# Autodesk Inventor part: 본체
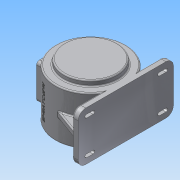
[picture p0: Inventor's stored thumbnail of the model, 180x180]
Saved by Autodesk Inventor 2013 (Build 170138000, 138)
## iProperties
Created: 2015-06
Part Number: 본체
Material: 알루미늄 6061
Document SubType Name: Modeling
Designer: Administrator
Density: 2.71 g/cm^3
Mass: 3338.13 g
Surface Area: 2328.16 cm^2
Volume: 1231.78 cm^3
Author: Administrator
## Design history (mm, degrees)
sketch "스케치2"
  geometry: C1 r 85 at (0, 0); 1 further point
  constraints: 1 centre point, 1 coincident
  dimensions: "d6" = 170 diameter of C1
extrude "돌출2" new body sketch "스케치2" distance "d7" = 118; taper "d8" = 0 deg
sketch "스케치3"
  geometry: C1 r 85 at (0, 0) reference; C2 r 65 at (0, 0)
  constraints: 1 centre point, 1 coincident
  dimensions: "d9" = 130 diameter of C2
extrude "돌출3" join sketch "스케치3" distance "d10" = 13; taper "d11" = 0 deg
sketch "스케치4"
  geometry: C1 r 85 at (0, 0) reference; C2 r 65 at (0, 0)
  constraints: 1 centre point, 1 coincident
  dimensions: "d12" = 130 diameter of C2
extrude "돌출4" join sketch "스케치4" distance "d13" = 3; taper "d14" = 0 deg
sketch "스케치8"
  geometry: L1 (-85, 0)-(-85, 118) reference; L2 (-85, 118)-(-65, 118) reference; L3 (-65, 118)-(-65, 131) reference; L4 (-65, 131)-(65, 131) reference; L5 (65, 131)-(65, 118) reference; L6 (65, 118)-(85, 118) reference; L7 (85, 118)-(85, 0) reference; L8 (85, 0)-(65, 0) reference; L9 (65, 0)-(65, -3) reference; L10 (65, -3)-(-65, -3) reference; L11 (-65, -3)-(-65, 0) reference; L12 (-65, 0)-(-85, 0) reference; L13 (15, 123.5)-(15, 120.5); L14 (15, 120.5)-(23.5, 120.5); L15 (23.5, 120.5)-(23.5, 106.5); L16 (23.5, 106.5)-(29.368, 106.5); L17 (29.368, 106.5)-(31, 110); L18 (31, 110)-(77, 110); L19 (77, 110)-(77, 8); L20 (77, 8)-(47.5, 8); L21 (47.5, 8)-(47.5, -3); L22 (15, 123.5)-(0, 123.5); L23 (0, 123.5)-(0, -3); L24 (47.5, -3)-(0, -3); 1 further point
  constraints: 24 end point, 2 perpendicular, 1 collinear, 1 midpoint, 1 point on line
  dimensions: "d64" = 3 distance between parallel lines of L14 L22; "d65" = 14 distance between parallel lines of L16 L14; "d66" = 3.5 distance between parallel lines of L16 L18; "d67" = 115 deg angle of L16 L17; "d68" = 102 distance between parallel lines of L18 L20; "d70" = 7.5 distance between parallel lines of L22 L4; "d71" = 154 diameter of L19 L23; "d72" = 47 diameter of L15 L23; "d73" = 30 diameter of L13 L23; "d74" = 62 diameter of L17.end L23; "d75" = 95 diameter of L21 L23
  node "절단 모서리 투영2"
revolve "회전1" stored, may be unused: angle "d76" = 90 deg
node "작업 평면2"
sketch "스케치9"
  geometry: L1 (-97, 118)-(97, 118); L2 (115, 100)-(115, 18); L3 (97, 0)-(-97, 0); L4 (-115, 18)-(-115, 100); L5 (0, 0)-(0, 118) reference; A1 r 18 centre (-97, 100) between (-97, 118) and (-115, 100); A2 r 18 centre (-97, 18) between (-115, 18) and (-97, 0); A3 r 18 centre (97, 18) between (97, 0) and (115, 18); A4 r 18 centre (97, 100) between (115, 100) and (97, 118); 6 further points
  constraints: 8 end point, 8 point on circle, 8 tangent, 6 point on line, 4 centre point, 3 equal radius, 3 midpoint, 2 parallel, 1 coincident, 1 horizontal, 1 horizontal alignment, 1 perpendicular
  dimensions: "d78" = 230 distance of point (-115, 118) point (115, 118); "d80" = 118 distance of point (-115, 0) point (-115, 118); "d81" = 18 radius of A1
extrude "돌출6" join sketch "스케치9" distance "d82" = 14; taper "d83" = 0 deg
sketch "스케치10"
  geometry: L1 (118, 46.733)-(118, 97) reference; L2 (0, 97)-(0, 46.733) reference; L3 (91, 97)-(91, 81); L4 (109, 81)-(109, 97); L5 (18, 115)-(100, 115) reference; L6 (118, 97)-(118, 46.733) reference; L7 (0, 46.733)-(118, 46.733) reference; L8 (0, -46.733)-(0, 46.733) reference; L9 (118, -46.733)-(0, -46.733) reference; L10 (118, -46.733)-(118, -97) reference; L11 (100, -115)-(18, -115) reference; L12 (0, -97)-(0, -46.733) reference; L13 (0, 46.733)-(0, 97) reference; L14 (118, 46.733)-(118, -46.733) reference; L15 (8, 29.799)-(8, -29.799) reference; L16 (8, -29.799)-(110, -29.799) reference; L17 (110, -29.799)-(110, 29.799) reference; L18 (110, 29.799)-(8, 29.799) reference; L19 (96, 97)-(96, 81); L20 (104, 81)-(104, 97); A1 r 18 centre (100, 97) between (118, 97) and (100, 115) reference; A2 r 9 centre (100, 81) between (91, 81) and (109, 81); A3 r 9 centre (100, 97) between (109, 97) and (91, 97); A4 r 18 centre (18, 97) between (18, 115) and (0, 97) reference; A5 r 18 centre (100, 97) between (118, 97) and (100, 115) reference; A6 r 18 centre (100, -97) between (100, -115) and (118, -97) reference; A7 r 18 centre (18, -97) between (0, -97) and (18, -115) reference; A8 r 4 centre (100, 81) between (96, 81) and (104, 81); A9 r 4 centre (100, 97) between (104, 97) and (96, 97); 1 further point
  constraints: 8 end point, 8 point on circle, 4 centre point, 3 tangent, 2 parallel, 1 coincident, 1 equal radius, 3 other
  dimensions: "d84" = 18 distance between parallel lines of L4 L3; "d86" = 16 distance of A2.centre A1.centre; "d87" = 8 distance between parallel lines of L20 L19
  node "절단 모서리 투영4"
extrude "돌출7" join sketch "스케치10" distance "d88" = 3; taper "d89" = 0 deg
extrude "돌출8" cut sketch "스케치10" distance "d90" = 3; taper "d92" = 0 deg; dims "d91" = 14, "d93" = 0
node "작업 평면3"
sketch "스케치11"
  geometry: L1 (71, -29.799)-(71, 29.799) reference; L2 (71, 46.733)-(71, 115) reference; L3 (71, 115)-(85, 115) reference; L4 (85, 115)-(85, -115) reference; L5 (85, -115)-(71, -115) reference; L6 (71, -115)-(71, -46.733) reference; L7 (71, -109)-(4.703, -84.87); L8 (71, 109)-(4.703, 84.87); A1 r 77 centre (0, 0) between (71, 29.799) and (71, -29.799) reference; A2 r 85 centre (0, 0) between (71, 46.733) and (71, -46.733) reference; 1 further point
  constraints: 4 end point, 2 point on circle, 2 point on line
  dimensions: "d101" = 6 distance of L7.start L5.end; "d102" = 110 deg angle of L7 L6; "d103" = 6 distance of L2.end L8.start; "d104" = 110 deg angle of L2 L8
  node "절단 모서리 투영5"
feature "리브1" dims "d105" = 1, "d106" = 15, "d107" = 0, "d108" = 0, "d109" = 1, "d110" = 1
feature "리브2" dims "d111" = 1, "d112" = 15, "d113" = 0, "d114" = 0, "d115" = 1, "d116" = 1
node "작업 평면4"
sketch "스케치12"
  geometry: L1 (-35.5, 101.5)-(35.5, 101.5); L2 (42.5, 94.5)-(42.5, 23.5); L3 (35.5, 16.5)-(-35.5, 16.5); L4 (-42.5, 23.5)-(-42.5, 94.5); L5 (115, 18)-(115, 100) reference; A1 r 7 centre (-35.5, 94.5) between (-35.5, 101.5) and (-42.5, 94.5); A2 r 7 centre (-35.5, 23.5) between (-42.5, 23.5) and (-35.5, 16.5); A3 r 7 centre (35.5, 23.5) between (35.5, 16.5) and (42.5, 23.5); A4 r 7 centre (35.5, 94.5) between (42.5, 94.5) and (35.5, 101.5); 8 further points
  constraints: 8 end point, 8 point on circle, 8 point on line, 8 tangent, 4 centre point, 3 equal radius, 3 midpoint, 2 parallel, 1 horizontal, 1 horizontal alignment, 1 perpendicular, 1 vertical alignment
  dimensions: "d118" = 85 distance between parallel lines of L2 L4; "d120" = 85 distance between parallel lines of L1 L3; "d127" = 7 radius of A1
extrude "돌출9" join sketch "스케치12" stored distance "d121" = 3; taper "d122" = 0 deg
sketch "스케치13"
  geometry: L1 (101.5, 35.5)-(101.5, -35.5) reference; L2 (23.5, 42.5)-(94.5, 42.5) reference; C1 r 35 at (59, 0); 6 further points
  constraints: 2 midpoint, 1 centre point, 1 horizontal alignment, 1 vertical alignment
  dimensions: "d123" = 70 diameter of C1
extrude "돌출10" cut sketch "스케치13" stored distance "d124" = 3; taper "d125" = 0 deg
fillet "모깎기1" dims "d126" = 3
fillet "모깎기2" dims "d128" = 3
fillet "모깎기3" dims "d129" = 3
chamfer "모따기1" distance "d130" = 1; stored, may be unused: second distance "d131" = 2, angle "d132" = 45 deg
fillet "모깎기4" dims "d133" = 3
fillet "모깎기5" dims "d134" = 0.3
fillet "모깎기6" dims "d135" = 3
hole "구멍2" diameter "d138" = 3.242; stored, may be unused: countersink angle "d142" = 90 deg, drill point angle "d144" = 118 deg; dims "d136" = 10, "d137" = 10, "d139" = 10, "d140" = 4, "d141" = 2, "d143" = 13
sketch "스케치14"
  geometry: C1 r 47.5 at (0, 0) reference; C2 r 65 at (0, 0) reference; C3 r 47.5 at (0, 0) reference; 1 further point
  constraints: 1 vertical alignment
  dimensions: "d152" = 55 distance of C1.centre point (0, 55)
hole "구멍3" sketch "스케치14" at (0, 55) diameter "d153" = 3.242; stored, may be unused: countersink angle "d157" = 90 deg, drill point angle "d159" = 0 deg; dims "d154" = 10, "d155" = 4, "d156" = 2, "d158" = 13
node "작업축1"
node "작업 평면6"
  node "작업 평면5"
node "작업축2"
  node "작업 평면7"
sketch "스케치15"
  geometry: L1 (101.243, -88.5)-(101.243, -6.5) reference; L2 (-16.09, 51.3)-(-16.09, -136.3) reference; 3 further points
  constraints: 1 horizontal alignment, 1 midpoint, 1 point on line, 1 other
feature "엠보싱1" sketch "스케치15" dims "d166" = 0.5, "d167" = 0
fillet "모깎기7" dims "d168" = 3
fillet "모깎기8" dims "d169" = 3
revolve "회전2" stored, may be unused: angle "d170" = 90 deg
fillet "모깎기9" dims "d171" = 3
fillet "모깎기10" dims "d172" = 0.3
fillet "모깎기11" dims "d173" = 3
chamfer "모따기2" distance "d174" = 1; stored, may be unused: second distance "d175" = 2, angle "d176" = 45 deg
node "솔리드2"
pattern_linear "직사각형 패턴1" dims "d96" = 83, "d99" = 176
pattern_linear "직사각형 패턴2" dims "d147" = 71, "d150" = 71
pattern_circular "원형 패턴1" dims angle "d161" = 360 deg
node "절단 모서리 투영3"
node "절단 모서리 투영6"
other parameters: "d77" = 85, "d100" = 59, "d117" = -173, "d163" = 75 deg, "d164" = -91.25, "d165" = -25 deg
